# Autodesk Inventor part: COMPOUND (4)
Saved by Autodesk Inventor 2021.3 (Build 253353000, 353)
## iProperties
Created: 2022-06
Part Number: COMPOUND (4)
Material: Generic
Document SubType Name: Modeling
Designer: Administrator
Density: 1 g/cm^3
Appearance: Default
Title: COMPOUND (4)
Author: Administrator
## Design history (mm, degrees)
feature "Body1"
body "Solid1"
